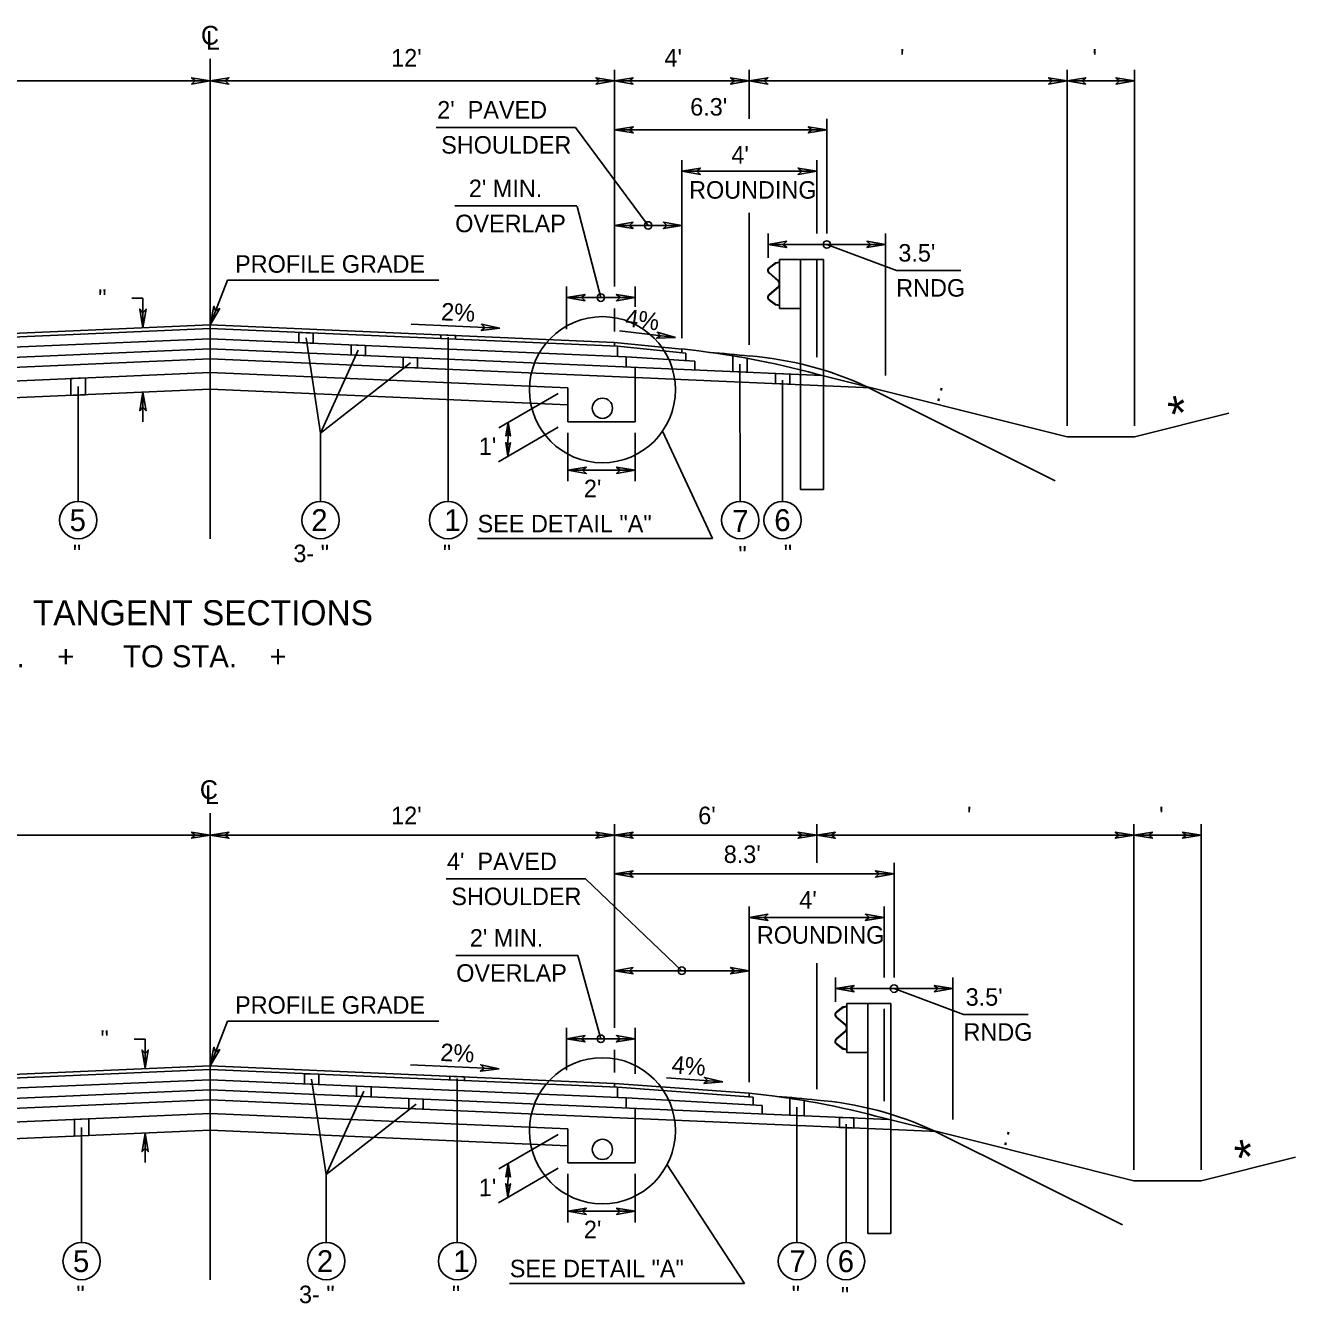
# Model space of a CAD drawing. Extents: x -592 to 1199, y -590 to 416.
# Drawn here: x 227.3 to 328.9, y 169.1 to 271.2 of the extents above; entities that cross this region are included whole.
import ezdxf

# ---------------------------------------------------------------- set-up
doc = ezdxf.new("R2010")
doc.units = 0
doc.layers.add('1', color=7, linetype='Continuous')
doc.layers.add('Des_ Drain_ Ftrs', color=7, linetype='Continuous')

msp = doc.modelspace()

# ---------------------------------------------------------------- linework, layer by layer
at = {"layer": '1'}
for p, q in [((242.09, 230.22), (242.09, 268.57)), ((274.42, 250.37), (274.42, 267.69)), ((285.19, 263.77), (285.19, 267.69)), ((310.61, 239.25), (310.61, 267.69)), ((316, 239.25), (316, 267.69)), ((242.09, 266.81), (209.76, 266.81)), ((242.09, 266.81), (274.42, 266.81)), ((274.42, 266.81), (285.19, 266.81)), ((285.19, 266.81), (310.61, 266.81)), ((310.61, 266.81), (316, 266.81)), ((291.39, 254.62), (291.39, 263.77)), ((271.3, 263.1), (260.16, 263.1)), ((277.11, 255.26), (271.3, 263.1)), ((274.42, 262.89), (291.39, 262.89)), ((279.8, 246.26), (279.8, 260.47)), ((290.58, 254.62), (290.58, 260.47)), ((279.8, 259.59), (290.58, 259.59)), ((261.65, 256.82), (271.41, 256.82)), ((273.32, 249.49), (271.42, 256.77)), ((285.19, 245.71), (285.19, 256.26)), ((274.42, 255.26), (279.8, 255.26)), ((286.7, 252.67), (286.7, 254.62)), ((296.08, 243.26), (296.08, 254.62)), ((286.7, 253.74), (296.08, 253.74)), ((291.39, 253.74), (296.95, 251.67)), ((287.3, 252.27), (286.78, 251.88)), ((287.61, 252.33), (287.3, 252.27)), ((287.61, 252.3), (287.31, 252.24)), ((287.61, 252.55), (287.61, 248.62)), ((287.61, 252.55), (289.3, 252.55)), ((289.3, 252.55), (289.3, 234.16)), ((291.12, 252.55), (289.3, 252.55)), ((290.58, 244.74), (290.58, 252.53)), ((291.12, 252.55), (291.12, 234.16)), ((286.77, 251.45), (287.5, 250.81)), ((286.78, 251.47), (287.52, 250.84)), ((287.31, 252.24), (286.8, 251.86)), ((296.95, 251.67), (302.1, 251.67)), ((242.09, 247.32), (243.46, 250.89)), ((260.38, 250.89), (243.46, 250.89)), ((270.57, 246.96), (270.57, 250.37)), ((276.06, 248.75), (276.06, 250.37)), ((287.5, 250.36), (286.77, 249.73)), ((287.52, 250.34), (286.78, 249.7)), ((287.58, 250.63), (287.58, 250.55)), ((287.61, 250.63), (287.61, 250.55)), ((236.71, 249.46), (235.83, 249.46)), ((236.71, 249.46), (236.71, 247.09)), ((270.57, 249.49), (276.06, 249.49)), ((286.78, 249.29), (287.3, 248.91)), ((286.8, 249.32), (287.31, 248.93)), ((274.42, 246.79), (274.42, 248.61)), ((287.3, 248.91), (287.61, 248.85)), ((287.31, 248.93), (287.61, 248.88)), ((287.61, 248.62), (289.3, 248.62)), ((209.75, 245.91), (242.09, 247.32)), ((274.42, 245.91), (242.09, 247.32)), ((258.17, 247.36), (265.25, 247.05)), ((208.81, 244.76), (242.09, 246.21)), ((209.52, 245.6), (242.09, 247.02)), ((274.66, 245.6), (242.09, 247.02)), ((275.36, 244.76), (242.09, 246.21)), ((249.75, 246.28), (250.91, 238.66)), ((261.11, 246.33), (261.11, 233.19)), ((279.29, 246.3), (274.82, 246.85)), ((193.17, 243.27), (242.09, 245.41)), ((291, 243.27), (242.09, 245.41)), ((253.93, 245.3), (250.91, 238.66)), ((274.41, 245.61), (274.41, 245.91)), ((279.8, 245.38), (274.42, 245.91)), ((280.11, 245.05), (274.66, 245.6)), ((274.66, 245.6), (274.66, 244.79)), ((279.8, 245.08), (279.8, 245.38)), ((189.24, 242.29), (242.09, 244.6)), ((270.58, 243.35), (242.09, 244.6)), ((258.1, 244.29), (250.91, 238.66)), ((280.84, 244.4), (275.36, 244.76)), ((275.36, 244.76), (275.36, 243.95)), ((280.11, 244.45), (280.11, 245.05)), ((280.84, 243.71), (280.84, 244.4)), ((284.44, 244.17), (284.47, 233.19)), ((286.7, 244.61), (286.7, 244.61)), ((213.5, 242.27), (242.09, 243.52)), ((270.68, 242.27), (242.09, 243.52)), ((276.06, 243.11), (270.58, 243.35)), ((276.06, 243.92), (276.06, 243.11)), ((276.06, 239.57), (276.06, 243.11)), ((294.93, 242.29), (276.06, 243.11)), ((290.58, 243.37), (310.61, 238.37)), ((213.5, 240.92), (242.09, 242.17)), ((231.54, 242.38), (231.54, 233.19)), ((270.68, 240.92), (242.09, 242.17)), ((270.68, 239.57), (270.68, 242.27)), ((270.68, 242.27), (270.68, 242.27)), ((287.85, 242.89), (287.85, 233.19)), ((294.58, 242.37), (309.64, 234.85)), ((236.71, 241.93), (236.71, 239.57)), ((269.91, 241.83), (265.16, 239.08)), ((323.53, 240.25), (316, 238.37)), ((269.91, 239.13), (265.14, 236.38)), ((265.92, 239.52), (265.9, 236.82)), ((270.68, 239.57), (276.06, 239.57)), ((250.91, 238.66), (250.91, 233.19)), ((270.68, 238.69), (270.68, 234.81)), ((276.06, 238.69), (276.06, 234.81)), ((278.26, 238.82), (282.24, 230.23)), ((310.61, 238.37), (316, 238.37)), ((270.68, 235.69), (276.06, 235.69)), ((291.12, 234.16), (289.3, 234.16)), ((263.46, 230.23), (282.24, 230.23)), ((242.09, 171), (242.09, 208.29)), ((274.42, 191.14), (274.42, 207.41)), ((290.58, 204.31), (290.58, 207.41)), ((315.94, 179.79), (315.94, 207.41)), ((321.33, 179.79), (321.33, 207.41)), ((242.09, 206.53), (209.76, 206.53)), ((242.09, 206.53), (274.42, 206.53)), ((274.42, 206.53), (290.58, 206.53)), ((290.58, 206.53), (315.94, 206.53)), ((315.94, 206.53), (321.33, 206.53)), ((296.77, 195.15), (296.77, 204.31)), ((274.41, 203.43), (296.77, 203.43)), ((272.1, 203.04), (260.96, 203.04)), ((279.8, 195.7), (272.1, 203.04)), ((285.19, 186.8), (285.19, 200.84)), ((295.97, 195.15), (295.97, 200.84)), ((285.19, 199.96), (295.97, 199.96)), ((261.72, 196.92), (271.49, 196.92)), ((273.32, 190.26), (271.49, 196.92)), ((290.58, 186.24), (290.58, 196.31)), ((274.42, 195.7), (285.19, 195.7)), ((292.08, 193.2), (292.08, 195.15)), ((301.46, 183.81), (301.46, 195.15)), ((292.08, 194.27), (301.46, 194.27)), ((296.77, 194.27), (302.33, 192.2)), ((292.99, 193.09), (292.99, 189.15)), ((292.99, 193.09), (294.68, 193.09)), ((294.68, 193.09), (294.68, 174.69)), ((296.5, 193.09), (294.68, 193.09)), ((296.5, 193.09), (296.5, 174.69)), ((292.68, 192.8), (292.16, 192.41)), ((292.17, 192), (292.9, 191.37)), ((292.69, 192.77), (292.18, 192.39)), ((292.99, 192.86), (292.68, 192.8)), ((292.99, 192.83), (292.69, 192.77)), ((295.97, 185.27), (295.97, 192.65)), ((302.33, 192.2), (307.48, 192.2)), ((242.09, 188.1), (243.46, 191.68)), ((260.38, 191.68), (243.46, 191.68)), ((270.57, 187.74), (270.57, 191.14)), ((276.06, 187.45), (276.06, 191.14)), ((292.15, 191.98), (292.88, 191.35)), ((292.96, 191.16), (292.96, 191.08)), ((292.99, 191.16), (292.99, 191.08)), ((236.89, 190.24), (236.01, 190.24)), ((236.89, 190.24), (236.89, 187.88)), ((270.57, 190.26), (276.06, 190.26)), ((292.88, 190.89), (292.15, 190.26)), ((292.9, 190.87), (292.17, 190.24)), ((274.42, 187.57), (274.42, 189.38)), ((292.16, 189.83), (292.68, 189.44)), ((292.18, 189.85), (292.69, 189.47)), ((292.68, 189.44), (292.99, 189.38)), ((292.69, 189.47), (292.99, 189.41)), ((292.99, 189.15), (294.68, 189.15)), ((209.75, 186.69), (242.09, 188.1)), ((274.41, 186.69), (242.09, 188.1)), ((258.11, 188.18), (265.19, 187.87)), ((208.81, 185.54), (242.09, 186.99)), ((209.52, 186.38), (242.09, 187.8)), ((274.66, 186.38), (242.09, 187.8)), ((275.36, 185.54), (242.09, 186.99)), ((250.2, 187.04), (251.37, 179.42)), ((261.83, 187.08), (261.83, 173.97)), ((283.07, 186.82), (278.58, 187.14)), ((187.83, 183.82), (242.09, 186.18)), ((296.33, 183.82), (242.09, 186.18)), ((254.38, 186.06), (251.37, 179.42)), ((285.19, 185.92), (274.41, 186.69)), ((274.41, 186.39), (274.41, 186.69)), ((285.5, 185.59), (274.66, 186.38)), ((274.66, 186.38), (274.66, 185.57)), ((285.19, 185.62), (285.19, 185.92)), ((213.6, 184.13), (242.09, 185.38)), ((270.58, 184.13), (242.09, 185.38)), ((258.55, 185.04), (251.37, 179.42)), ((275.36, 185.54), (275.36, 184.74)), ((286.22, 184.94), (275.36, 185.54)), ((285.5, 184.98), (285.5, 185.59)), ((286.22, 184.26), (286.22, 184.94)), ((292.08, 185.14), (292.08, 185.14)), ((213.5, 183.05), (242.09, 184.3)), ((270.68, 183.05), (242.09, 184.3)), ((276.06, 183.89), (270.58, 184.13)), ((276.06, 184.7), (276.06, 183.89)), ((276.06, 180.35), (276.06, 183.89)), ((300.25, 182.84), (276.06, 183.89)), ((289, 184.8), (289, 173.97)), ((295.97, 183.91), (315.94, 178.91)), ((213.5, 181.7), (242.09, 182.95)), ((231.81, 183.18), (231.81, 173.97)), ((270.68, 181.7), (242.09, 182.95)), ((270.68, 180.35), (270.68, 183.05)), ((270.68, 183.05), (270.68, 183.05)), ((292.93, 183.44), (292.93, 173.97)), ((299.96, 182.91), (315.02, 175.38)), ((236.89, 182.72), (236.89, 180.36)), ((269.91, 182.61), (265.16, 179.86)), ((328.86, 180.8), (321.33, 178.91)), ((269.91, 179.91), (265.14, 177.16)), ((265.92, 180.3), (265.9, 177.59)), ((270.68, 180.35), (276.06, 180.35)), ((278.62, 180.18), (284.82, 170.7)), ((251.37, 179.42), (251.37, 173.97)), ((270.68, 179.47), (270.68, 175.59)), ((276.06, 179.47), (276.06, 175.59)), ((315.94, 178.91), (321.33, 178.91)), ((270.68, 176.47), (276.06, 176.47)), ((296.5, 174.69), (294.68, 174.69)), ((266.03, 170.7), (284.82, 170.7))]:
    msp.add_line(p, q, dxfattribs=at)
for points in [[(249.18, 246.71), (250.32, 246.66), (250.32, 245.85), (249.18, 245.9)], [(260.54, 246.52), (261.69, 246.47), (261.69, 246.17), (260.54, 246.22)], [(253.35, 245.72), (254.5, 245.67), (254.5, 244.86), (253.35, 244.91)], [(257.53, 244.73), (258.67, 244.68), (258.67, 243.87), (257.53, 243.92)], [(283.87, 244.84), (285.02, 244.64), (285.02, 243.53), (283.87, 243.58)], [(230.96, 243.03), (232.11, 243.08), (232.11, 241.73), (230.96, 241.68)], [(287.29, 243.43), (288.44, 243.38), (288.44, 242.57), (287.29, 242.62)], [(249.63, 187.47), (250.78, 187.42), (250.78, 186.61), (249.63, 186.66)], [(261.26, 187.27), (262.41, 187.22), (262.41, 186.92), (261.26, 186.97)], [(253.8, 186.48), (254.95, 186.43), (254.95, 185.62), (253.8, 185.67)], [(257.98, 185.49), (259.13, 185.44), (259.13, 184.63), (257.98, 184.68)], [(288.43, 185.5), (289.57, 185.32), (289.57, 184.11), (288.43, 184.16)], [(231.24, 183.82), (232.38, 183.87), (232.38, 182.52), (231.24, 182.47)], [(292.4, 183.98), (293.55, 183.93), (293.55, 183.12), (292.4, 183.17)]]:
    msp.add_lwpolyline(points, close=True, dxfattribs=at)
for centre, radius in [((277.11, 255.26), 0.3), ((291.39, 253.74), 0.3), ((273.32, 249.49), 0.3), ((273.45, 242.13), 5.84), ((273.45, 240.65), 0.808), ((231.54, 231.71), 1.49), ((250.91, 231.71), 1.49), ((261.11, 231.71), 1.49), ((284.47, 231.71), 1.49), ((287.85, 231.71), 1.49), ((279.8, 195.7), 0.3), ((296.77, 194.27), 0.3), ((273.32, 190.26), 0.3), ((273.45, 182.91), 5.84), ((273.45, 181.42), 0.808), ((231.81, 172.49), 1.49), ((251.37, 172.49), 1.49), ((261.83, 172.49), 1.49), ((289, 172.49), 1.49), ((292.93, 172.49), 1.49)]:
    msp.add_circle(centre, radius, dxfattribs=at)
for centre, radius, start, end in [((286.95, 251.66), 0.278, 126.9799, 229.021), ((286.95, 251.66), 0.249, 126.9799, 229.021), ((287.33, 250.63), 0.249, 0, 49.0365), ((287.33, 250.55), 0.249, 310.9635, 0), ((287.33, 250.63), 0.278, 0, 49.0365), ((287.33, 250.55), 0.278, 310.9635, 0), ((286.95, 249.52), 0.278, 130.979, 233.0201), ((286.95, 249.52), 0.249, 130.979, 233.0201), ((272.92, 178.55), 67.19, 74.7593, 84.1179), ((274.38, 144.16), 101.24, 83.8633, 85.6775), ((283.08, 217.54), 27.37, 65.1374, 85.5513), ((292.33, 192.19), 0.278, 126.9799, 229.021), ((292.33, 192.19), 0.249, 126.9799, 229.021), ((292.71, 191.16), 0.249, 0, 49.0365), ((292.71, 191.08), 0.249, 310.9635, 0), ((292.71, 191.16), 0.278, 0, 49.0365), ((292.71, 191.08), 0.278, 310.9635, 0), ((292.33, 190.05), 0.278, 130.979, 233.0201), ((292.33, 190.05), 0.249, 130.979, 233.0201), ((278.31, 119.08), 67.19, 74.7611, 84.1196), ((279.76, 84.7), 101.24, 83.8633, 85.6775), ((288.46, 158.07), 27.37, 65.1374, 85.5513)]:
    msp.add_arc(centre, radius, start, end, dxfattribs=at)
at = {"layer": 'Des_ Drain_ Ftrs'}
for points in [[(242.09, 266.81), (240.6, 266.56), (240.89, 266.81), (240.6, 267.06)], [(242.09, 266.81), (243.58, 266.56), (243.28, 266.81), (243.58, 267.06)], [(274.42, 266.81), (272.93, 266.56), (273.22, 266.81), (272.93, 267.06)], [(274.42, 266.81), (275.9, 266.56), (275.61, 266.81), (275.9, 267.06)], [(285.19, 266.81), (283.7, 266.56), (284, 266.81), (283.7, 267.06)], [(285.19, 266.81), (286.68, 266.56), (286.39, 266.81), (286.68, 267.06)], [(310.61, 266.81), (309.12, 266.56), (309.42, 266.81), (309.12, 267.06)], [(310.61, 266.81), (312.1, 266.56), (311.8, 266.81), (312.1, 267.06)], [(316, 266.81), (314.51, 266.56), (314.8, 266.81), (314.51, 267.06)], [(274.42, 262.89), (275.91, 262.65), (275.61, 262.89), (275.91, 263.14)], [(291.39, 262.89), (289.9, 262.65), (290.2, 262.89), (289.9, 263.14)], [(279.8, 259.59), (281.29, 259.34), (281, 259.59), (281.29, 259.84)], [(290.58, 259.59), (289.09, 259.34), (289.39, 259.59), (289.09, 259.84)], [(274.42, 255.26), (275.9, 255.01), (275.61, 255.26), (275.9, 255.51)], [(279.8, 255.26), (278.32, 255.01), (278.61, 255.26), (278.32, 255.51)], [(286.7, 253.74), (288.19, 253.49), (287.89, 253.74), (288.19, 253.99)], [(296.08, 253.74), (294.6, 253.49), (294.89, 253.74), (294.6, 253.99)], [(270.57, 249.49), (272.06, 249.24), (271.77, 249.49), (272.06, 249.74)], [(276.06, 249.49), (274.57, 249.24), (274.87, 249.49), (274.57, 249.74)], [(236.71, 247.09), (236.96, 248.58), (236.71, 248.28), (236.46, 248.58)], [(242.09, 247.32), (242.85, 248.62), (242.51, 248.44), (242.39, 248.8)], [(265.25, 247.05), (263.76, 246.87), (264.06, 247.1), (263.78, 247.36)], [(279.29, 246.3), (277.78, 246.24), (278.1, 246.45), (277.84, 246.73)], [(236.71, 241.93), (236.96, 240.45), (236.71, 240.74), (236.46, 240.45)], [(265.92, 239.52), (265.73, 238.44), (265.91, 238.65), (266.09, 238.44)], [(265.9, 236.82), (265.72, 237.9), (265.9, 237.69), (266.09, 237.9)], [(270.68, 235.69), (272.16, 235.44), (271.87, 235.69), (272.16, 235.94)], [(276.06, 235.69), (274.58, 235.44), (274.87, 235.69), (274.58, 235.94)], [(242.09, 206.53), (240.6, 206.28), (240.89, 206.53), (240.6, 206.77)], [(242.09, 206.53), (243.58, 206.28), (243.28, 206.53), (243.58, 206.77)], [(274.42, 206.53), (272.93, 206.28), (273.22, 206.53), (272.93, 206.77)], [(274.42, 206.53), (275.9, 206.28), (275.61, 206.53), (275.9, 206.77)], [(290.58, 206.53), (289.09, 206.28), (289.39, 206.53), (289.09, 206.77)], [(290.58, 206.53), (292.07, 206.28), (291.77, 206.53), (292.07, 206.77)], [(315.94, 206.53), (314.45, 206.28), (314.74, 206.53), (314.45, 206.77)], [(315.94, 206.53), (317.43, 206.28), (317.13, 206.53), (317.43, 206.77)], [(321.33, 206.53), (319.84, 206.28), (320.13, 206.53), (319.84, 206.77)], [(274.41, 203.43), (275.9, 203.18), (275.6, 203.43), (275.9, 203.67)], [(296.77, 203.43), (295.28, 203.18), (295.58, 203.43), (295.28, 203.67)], [(285.19, 199.96), (286.68, 199.72), (286.39, 199.96), (286.68, 200.21)], [(295.97, 199.96), (294.48, 199.72), (294.78, 199.96), (294.48, 200.21)], [(274.42, 195.7), (275.9, 195.45), (275.61, 195.7), (275.9, 195.95)], [(285.19, 195.7), (283.7, 195.45), (284, 195.7), (283.7, 195.95)], [(292.08, 194.27), (293.57, 194.02), (293.27, 194.27), (293.57, 194.52)], [(301.46, 194.27), (299.98, 194.02), (300.27, 194.27), (299.98, 194.52)], [(270.57, 190.26), (272.06, 190.01), (271.77, 190.26), (272.06, 190.51)], [(276.06, 190.26), (274.57, 190.01), (274.87, 190.26), (274.57, 190.51)], [(236.89, 187.88), (237.14, 189.36), (236.89, 189.07), (236.64, 189.36)], [(242.09, 188.1), (242.85, 189.4), (242.51, 189.22), (242.39, 189.58)], [(265.19, 187.87), (263.7, 187.68), (264, 187.92), (263.72, 188.18)], [(283.07, 186.82), (281.56, 186.68), (281.88, 186.9), (281.6, 187.17)], [(236.89, 182.72), (237.14, 181.24), (236.89, 181.53), (236.64, 181.24)], [(265.92, 180.3), (265.73, 179.22), (265.91, 179.43), (266.09, 179.21)], [(265.9, 177.59), (265.72, 178.68), (265.9, 178.46), (266.09, 178.68)], [(270.68, 176.47), (272.16, 176.22), (271.87, 176.47), (272.16, 176.72)], [(276.06, 176.47), (274.58, 176.22), (274.87, 176.47), (274.58, 176.72)]]:
    msp.add_lwpolyline(points, close=True, dxfattribs=at)

# ---------------------------------------------------------------- texts
at = {"layer": '1'}
for s, height, p in [("12'", 1.4, (256.56, 267.96)), ("4'", 1.4, (278.41, 267.96)), ("  '", 1.4, (296.2, 267.96)), (" '", 1.4, (312.11, 267.96)), ("2'  PAVED", 1.4, (260.24, 263.8)), ("6.3'", 1.4, (280.47, 264.04)), ('SHOULDER', 1.4, (260.56, 261)), ("4'", 1.4, (283.76, 260.2)), ("2' MIN.", 1.4, (262.77, 257.52)), ('ROUNDING', 1.4, (280.38, 257.4)), ('OVERLAP', 1.4, (261.68, 254.72)), ("3.5'", 1.4, (297.11, 252.37)), ('PROFILE GRADE', 1.4, (244.08, 251.48)), ('RNDG', 1.4, (296.94, 249.57)), ("2'", 1.4, (271.97, 233.54)), ('5', 1.75, (230.85, 230.83)), ('2', 1.75, (250.17, 230.83)), ('1', 1.75, (260.81, 230.83)), ('SEE DETAIL "A"', 1.4, (263.47, 230.73)), ('7', 1.75, (283.83, 230.76)), ('6', 1.75, (287.19, 230.83)), (' "', 1.4, (230.59, 228.35)), ('3- "', 1.4, (248.74, 228.35)), (' "', 1.4, (260.17, 228.35)), (' "', 1.4, (283.8, 228.25)), (' "', 1.4, (287.43, 228.35)), ('TANGENT SECTIONS', 2, (227.91, 223.31)), ('STA.    +      TO STA.    +     ', 1.75, (222.06, 219.95)), ("12'", 1.4, (256.56, 207.41)), ("6'", 1.4, (281.11, 207.41)), ("  '", 1.4, (301.56, 207.41)), (" '", 1.4, (317.44, 207.41)), ("8.3'", 1.4, (283.15, 204.31)), ("4'  PAVED", 1.4, (261.02, 203.74)), ('SHOULDER', 1.4, (261.37, 200.94)), ("4'", 1.4, (289.19, 200.66)), ('ROUNDING', 1.4, (285.8, 197.86)), ("2' MIN.", 1.4, (262.85, 197.62)), ('OVERLAP', 1.4, (261.76, 194.82)), ("3.5'", 1.4, (302.49, 192.9)), ('PROFILE GRADE', 1.4, (244.08, 192.26)), ('RNDG', 1.4, (302.32, 190.1)), ("2'", 1.4, (271.97, 174.32)), ('5', 1.75, (231.12, 171.61)), ('2', 1.75, (250.62, 171.61)), ('1', 1.75, (261.53, 171.61)), ('SEE DETAIL "A"', 1.4, (266.04, 171.2)), ('7', 1.75, (288.41, 171.61)), ('6', 1.75, (292.27, 171.61)), (' "', 1.4, (230.87, 169.13)), ('3- "', 1.4, (249.19, 169.13)), (' "', 1.4, (260.89, 169.13)), (' "', 1.4, (288.06, 169.13)), (' "', 1.4, (291.99, 169.03))]:
    msp.add_text(s, height=height, dxfattribs=at).set_placement(p)
for s, height, rotation, p in [('  "', 1.4, 0.1438, (232.1, 248.75)), ('2%', 1.4, 357.3765, (260.53, 247.68)), ('4%', 1.4, 352.7159, (275.21, 247.2)), (' : ', 1.4, 345.7718, (299.55, 241.42)), ('*', 2.8, 12.8479, (319.09, 238.72)), ("1'", 1.4, 0.1438, (263.57, 236.91)), ('  "', 1.4, 0.1438, (232.28, 189.54)), ('2%', 1.4, 357.3763, (260.47, 188.49)), ('4%', 1.4, 355.6008, (278.95, 187.51)), (' : ', 1.4, 345.7718, (304.9, 181.96)), ('*', 2.8, 12.8479, (324.42, 179.27)), ("1'", 1.4, 0.1438, (263.57, 177.68))]:
    msp.add_text(s, height=height, rotation=rotation, dxfattribs=at).set_placement(p)
at = {"layer": 'Des_ Drain_ Ftrs'}
for s, p in [('C', (241.35, 269.71)), ('L', (241.74, 269.31)), ('C', (241.26, 209.42)), ('L', (241.66, 209.02))]:
    msp.add_text(s, height=1.5, dxfattribs=at).set_placement(p)

doc.saveas('drawing.dxf')
